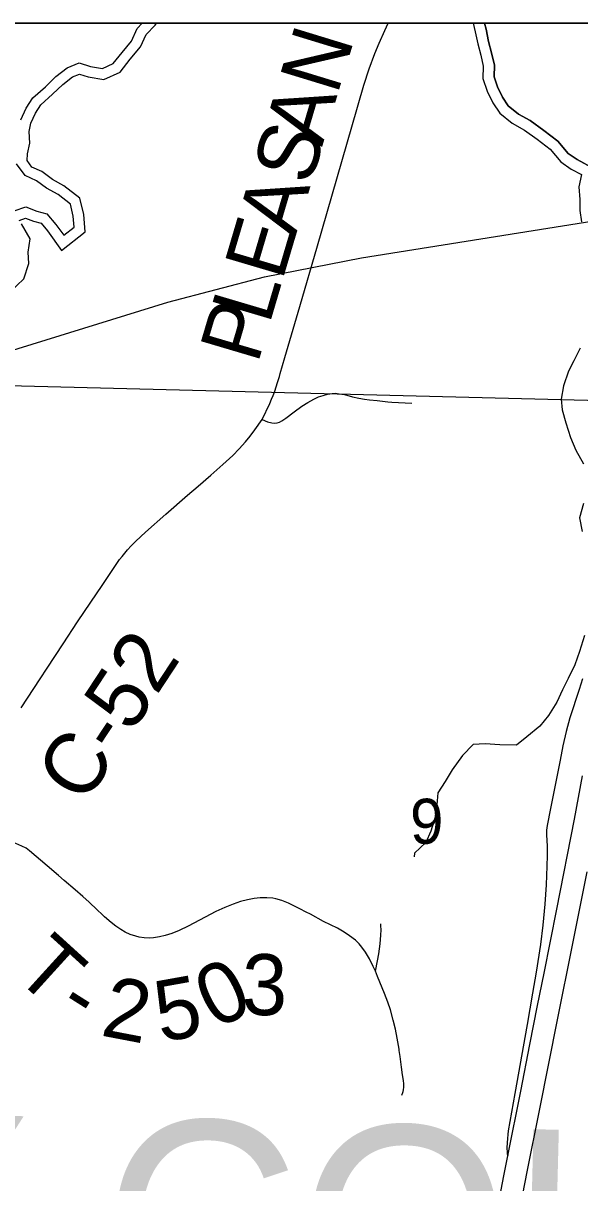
# Model space of a CAD drawing. Extents: x 0 to 34, y 0 to 22.
# Drawn here: x 7.568 to 8.087, y 19.819 to 20.9 of the extents above; entities that cross this region are included whole.
import ezdxf

# ---------------------------------------------------------------- set-up
doc = ezdxf.new("R2010")
doc.units = 0
for name, color, linetype in [('GM_X_Corporation', 7, 'Continuous'), ('GM_X_County_Road', 7, 'Continuous'), ('GM_X_County_Road_Text', 7, 'Continuous'), ('GM_X_County_Text', 7, 'Continuous'), ('GM_X_Interchange_Ramps', 7, 'Continuous'), ('GM_X_Interstate_Route', 7, 'Continuous'), ('GM_X_Major_River', 7, 'Continuous'), ('GM_X_Minor_River', 7, 'Continuous'), ('GM_X_Rail_Line', 7, 'Continuous'), ('GM_X_Section_Text', 7, 'Continuous'), ('GM_X_Township_Road', 7, 'Continuous'), ('GM_X_Township_Road_Text', 7, 'Continuous'), ('SH_Data', 7, 'Continuous')]:
    doc.layers.add(name, color=color, linetype=linetype)

msp = doc.modelspace()

# ---------------------------------------------------------------- linework, layer by layer
at = {"layer": 'GM_X_Corporation'}
for points in [[(8.9, 20.9), (2.1, 20.9), (2.1, 15.6606)], [(8.9, 20.9), (3.3886, 20.9), (3.3869, 20.7918), (3.3724, 19.7263), (3.3691, 19.5041), (3.3642, 18.7005)]]:
    msp.add_lwpolyline(points, dxfattribs=at)
for points in [[(8.4703, 20.9), (7.4509, 20.9), (7.4437, 20.565), (8.4622, 20.5392)], [(8.4622, 20.5392), (8.4405, 19.5256), (7.4231, 19.5526), (7.4437, 20.565)]]:
    msp.add_lwpolyline(points, close=True, dxfattribs=at)
at = {"layer": 'GM_X_County_Road'}
for points in [[(7.8079, 20.5734), (7.8121, 20.5883), (7.8262, 20.636), (7.8425, 20.6926), (7.8746, 20.8035), (7.8859, 20.8422), (7.8908, 20.8576), (7.8959, 20.8716), (7.8999, 20.8813), (7.9052, 20.8932), (7.9085, 20.9)], [(7.7909, 20.5305), (7.798, 20.5455), (7.7998, 20.5496), (7.8011, 20.5529), (7.8027, 20.5572), (7.8054, 20.5651), (7.8071, 20.5706), (7.8079, 20.5734)], [(7.5663, 20.2619), (7.5841, 20.2889), (7.5905, 20.2988), (7.6056, 20.3216), (7.6188, 20.342), (7.6314, 20.3604), (7.6418, 20.3759), (7.6518, 20.391), (7.6581, 20.4001), (7.6604, 20.403), (7.6655, 20.4092), (7.6688, 20.4129), (7.6731, 20.4172), (7.6822, 20.4257), (7.7013, 20.4425), (7.7215, 20.4601), (7.7314, 20.4686), (7.743, 20.4789), (7.7543, 20.4887), (7.7635, 20.497), (7.7697, 20.5032), (7.7756, 20.5097), (7.7799, 20.515), (7.7843, 20.5211), (7.7909, 20.5305)]]:
    msp.add_lwpolyline(points, dxfattribs=at)
at = {"layer": 'GM_X_Interchange_Ramps'}
msp.add_lwpolyline([(8.0896, 20.2891), (8.0864, 20.2791), (8.0777, 20.2525), (8.0742, 20.24), (8.0713, 20.2266), (8.0687, 20.2132), (8.0597, 20.1681), (8.0565, 20.1523), (8.0561, 20.148), (8.056, 20.1436), (8.0565, 20.1331), (8.0565, 20.1244), (8.0563, 20.1144), (8.0556, 20.0971), (8.0544, 20.0791), (8.0526, 20.0593), (8.0504, 20.0414), (8.0464, 20.0156), (8.0431, 19.996), (8.0379, 19.9667), (8.0265, 19.9025), (8.0204, 19.8677), (8.0199, 19.8644), (8.0197, 19.8606), (8.0191, 19.8523), (8.0191, 19.8508), (8.0192, 19.8484), (8.0195, 19.8463), (8.0201, 19.8444)], dxfattribs=at)
at = {"layer": 'GM_X_Interstate_Route'}
for points in [[(7.9586, 19.5353), (7.9699, 19.591), (7.982, 19.6525), (7.9896, 19.6903), (8.0023, 19.7556), (8.0115, 19.8012), (8.0163, 19.8258), (8.0201, 19.8444), (8.032, 19.9048), (8.0405, 19.9481), (8.0477, 19.9846), (8.0537, 20.0145), (8.0655, 20.0742), (8.0821, 20.1583), (8.0896, 20.1986)], [(7.9797, 19.5348), (7.9871, 19.5723), (7.9994, 19.6332), (8.0103, 19.6881), (8.0172, 19.7235), (8.0282, 19.7783), (8.0381, 19.8295), (8.0494, 19.8868), (8.0667, 19.9727), (8.0798, 20.0391), (8.0938, 20.1091)]]:
    msp.add_lwpolyline(points, dxfattribs=at)
at = {"layer": 'GM_X_Major_River'}
for points in [[(7.5645, 20.7162), (7.5704, 20.7184), (7.5778, 20.7155), (7.5849, 20.7135), (7.591, 20.7064), (7.604, 20.6883), (7.626, 20.7056), (7.6247, 20.7218), (7.6209, 20.7368), (7.6062, 20.7484), (7.5955, 20.7544), (7.5856, 20.7617), (7.5764, 20.7659), (7.572, 20.7719), (7.5724, 20.7783), (7.5743, 20.7883), (7.5738, 20.7992), (7.5755, 20.8069), (7.5796, 20.8162), (7.5848, 20.824), (7.5956, 20.8337), (7.6051, 20.843), (7.6141, 20.8499), (7.6208, 20.8526), (7.6287, 20.8499), (7.6435, 20.8475), (7.6585, 20.8544), (7.6681, 20.8665), (7.6775, 20.8781), (7.6829, 20.8896), (7.6911, 20.8983), (7.6924, 20.9)], [(7.5645, 20.7162), (7.5704, 20.7184), (7.5778, 20.7155), (7.5849, 20.7135), (7.591, 20.7064), (7.604, 20.6883), (7.626, 20.7056), (7.6247, 20.7218), (7.6209, 20.7368), (7.6062, 20.7484), (7.5955, 20.7544), (7.5856, 20.7617), (7.5764, 20.7659), (7.572, 20.7719), (7.5724, 20.7783), (7.5743, 20.7883), (7.5738, 20.7992), (7.5755, 20.8069), (7.5796, 20.8162), (7.5848, 20.824), (7.5956, 20.8337), (7.6051, 20.843), (7.6141, 20.8499), (7.6208, 20.8526), (7.6287, 20.8499), (7.6435, 20.8475), (7.6585, 20.8544), (7.6681, 20.8665), (7.6775, 20.8781), (7.6829, 20.8896), (7.6911, 20.8983), (7.6924, 20.9)], [(7.5661, 20.8099), (7.571, 20.8209), (7.5773, 20.8305), (7.5889, 20.8408), (7.5987, 20.8504), (7.6092, 20.8585), (7.6205, 20.8631), (7.6311, 20.8595), (7.6421, 20.8577), (7.6522, 20.8623), (7.6605, 20.8727), (7.6691, 20.8834), (7.6746, 20.8952), (7.6792, 20.9)], [(7.9876, 20.9), (7.9896, 20.892), (7.9919, 20.8807), (7.9947, 20.8701), (7.997, 20.8599), (7.9968, 20.8485), (8.0006, 20.8368), (8.006, 20.8259), (8.0125, 20.8161), (8.024, 20.8067), (8.0354, 20.8004), (8.0472, 20.7918), (8.0593, 20.7825), (8.0693, 20.7708), (8.0791, 20.7641), (8.0886, 20.7589), (8.0861, 20.7475), (8.087, 20.7358), (8.087, 20.7255), (8.0886, 20.715)], [(7.9983, 20.9), (7.9997, 20.8943), (8.002, 20.883), (8.0048, 20.8725), (8.0074, 20.8609), (8.0072, 20.8501), (8.0103, 20.8407), (8.015, 20.8311), (8.0203, 20.8231), (8.0298, 20.8153), (8.0409, 20.8092), (8.0534, 20.8001), (8.0665, 20.79), (8.0762, 20.7786), (8.0846, 20.773), (8.1005, 20.7643)], [(8.1005, 20.7643), (8.0846, 20.773), (8.0762, 20.7786), (8.0665, 20.79), (8.0534, 20.8001), (8.0409, 20.8092), (8.0298, 20.8153), (8.0203, 20.8231), (8.015, 20.8311), (8.0103, 20.8407), (8.0072, 20.8501), (8.0074, 20.8609), (8.0048, 20.8725), (8.002, 20.883), (7.9997, 20.8943), (7.9983, 20.9)], [(7.5597, 20.725), (7.5706, 20.7289), (7.5809, 20.7248), (7.5903, 20.7223), (7.5987, 20.7125), (7.606, 20.7023), (7.6158, 20.71), (7.6149, 20.7202), (7.6122, 20.7312), (7.6008, 20.7402), (7.5901, 20.7461), (7.5806, 20.7532), (7.57, 20.758), (7.562, 20.7689)], [(7.5558, 20.6494), (7.5688, 20.6616), (7.5734, 20.6759), (7.5729, 20.6866), (7.5747, 20.6989), (7.5666, 20.7131)], [(7.5558, 20.6494), (7.5688, 20.6616), (7.5734, 20.6759), (7.5729, 20.6866), (7.5747, 20.6989), (7.5666, 20.7131)]]:
    msp.add_lwpolyline(points, dxfattribs=at)
at = {"layer": 'GM_X_Minor_River'}
for points in [[(8.0874, 20.5971), (8.0815, 20.5853), (8.0766, 20.5758), (8.0718, 20.5621), (8.0697, 20.5496), (8.0705, 20.5397), (8.074, 20.5276), (8.0783, 20.514), (8.0833, 20.502), (8.0906, 20.4892)], [(8.0906, 20.4524), (8.0869, 20.4391), (8.0893, 20.4263)], [(8.0913, 20.3293), (8.0869, 20.3145), (8.0824, 20.3019), (8.0761, 20.2893), (8.0709, 20.2787), (8.0657, 20.2673), (8.0579, 20.2547), (8.0497, 20.2447), (8.0376, 20.2348), (8.0279, 20.2271), (8.0124, 20.2273), (7.9988, 20.2283), (7.9878, 20.2278), (7.9777, 20.2175), (7.968, 20.2041), (7.9616, 20.1934), (7.9546, 20.1828), (7.9539, 20.1714), (7.9521, 20.16), (7.9481, 20.1471), (7.9436, 20.1364), (7.9331, 20.1265), (7.9328, 20.123)]]:
    msp.add_lwpolyline(points, dxfattribs=at)
at = {"layer": 'GM_X_Rail_Line'}
msp.add_lwpolyline([(7.1538, 20.4701), (7.703, 20.6401), (7.7933, 20.6637), (7.8836, 20.6812), (8.2172, 20.7345), (8.3229, 20.7499), (8.4174, 20.7612), (8.4882, 20.7632), (8.5498, 20.7663), (8.589, 20.7738), (8.6669, 20.8033), (8.718, 20.8157), (8.9, 20.8406)], dxfattribs=at)
at = {"layer": 'GM_X_Township_Road'}
for points in [[(7.7909, 20.5305), (7.7961, 20.5285), (7.7999, 20.5275), (7.8024, 20.5273), (7.8049, 20.5275), (7.8072, 20.5283), (7.8094, 20.5294), (7.813, 20.5318), (7.8209, 20.5379), (7.828, 20.543), (7.8337, 20.5466), (7.8391, 20.5496), (7.8436, 20.5517), (7.8477, 20.5531), (7.8518, 20.5542), (7.8561, 20.5548), (7.8593, 20.5551), (7.8629, 20.5547), (7.8677, 20.5538), (7.8753, 20.5519), (7.8812, 20.5504), (7.8863, 20.5496), (7.8911, 20.549), (7.8981, 20.5483), (7.908, 20.5472), (7.9117, 20.5468), (7.9306, 20.5459)], [(7.6013, 20.1057), (7.5906, 20.1147), (7.574, 20.1288), (7.571, 20.131), (7.5671, 20.133), (7.5615, 20.1355), (7.5544, 20.138), (7.5412, 20.1426), (7.5344, 20.1449)], [(7.8965, 20.0166), (7.8944, 20.0208), (7.8909, 20.028), (7.8874, 20.0342), (7.8839, 20.039), (7.8813, 20.0421), (7.8779, 20.0453), (7.8724, 20.0496), (7.8673, 20.0528), (7.8611, 20.0565), (7.8482, 20.0628), (7.8359, 20.0696), (7.832, 20.0715), (7.826, 20.0745), (7.8155, 20.0798), (7.8092, 20.0824), (7.8038, 20.0839), (7.8008, 20.0845), (7.7953, 20.085), (7.7891, 20.0849), (7.7835, 20.0842), (7.7774, 20.083), (7.7708, 20.0813), (7.7638, 20.0789), (7.7563, 20.0759), (7.7479, 20.072), (7.7379, 20.0668), (7.722, 20.0584), (7.7136, 20.0544), (7.7067, 20.0516), (7.7007, 20.0497), (7.6953, 20.0484), (7.6898, 20.0475), (7.6861, 20.0473), (7.6811, 20.0475), (7.6762, 20.0483), (7.6732, 20.049), (7.6679, 20.0508), (7.6634, 20.0529), (7.6591, 20.0554), (7.6545, 20.0586), (7.6501, 20.062), (7.6441, 20.0673), (7.6351, 20.0758), (7.6319, 20.0787), (7.6297, 20.0808), (7.6237, 20.0861), (7.6166, 20.0922), (7.6063, 20.1011), (7.6013, 20.1057)], [(7.8965, 20.0166), (7.8984, 20.0262), (7.8997, 20.0328), (7.9009, 20.042), (7.9016, 20.0501), (7.9018, 20.055), (7.9017, 20.0588), (7.9015, 20.0606)], [(7.9211, 19.9011), (7.9221, 19.9033), (7.9224, 19.9044), (7.9228, 19.906), (7.9231, 19.9084), (7.9231, 19.9114), (7.9227, 19.9145), (7.9219, 19.92), (7.9209, 19.9272), (7.9198, 19.9345), (7.9195, 19.937), (7.9188, 19.9425), (7.9186, 19.9437), (7.9169, 19.9541), (7.9153, 19.9626), (7.9132, 19.971), (7.9105, 19.9805), (7.9081, 19.9876), (7.905, 19.9956), (7.8986, 20.0116), (7.8965, 20.0166)]]:
    msp.add_lwpolyline(points, dxfattribs=at)
at = {"layer": 'SH_Data'}
msp.add_line((2.1, 20.9), (8.9, 20.9), dxfattribs=at)

# ---------------------------------------------------------------- texts
at = {"layer": 'GM_X_County_Road_Text'}
for s, height, rotation, p in [('N', 0.0568, 73.0023, (7.8609, 20.8322)), ('A', 0.0568, 73.5007, (7.8468, 20.7844)), ('S', 0.0568, 73.5044, (7.8359, 20.7477)), ('A', 0.0568, 73.5082, (7.8217, 20.6997)), ('E', 0.0568, 73.506, (7.8096, 20.659)), ('L', 0.0568, 73.5047, (7.7976, 20.6182)), ('P', 0.0568, 73.5044, (7.7867, 20.5815)), ('C-52', 0.05682, 56.6824, (7.6252, 20.1705))]:
    msp.add_text(s, height=height, rotation=rotation, dxfattribs=at).set_placement(p)
at = {"layer": 'GM_X_County_Text'}
msp.add_text('GUERNSEY COUNTY', height=0.189394, rotation=358.543, dxfattribs=at).set_placement((6.1485, 19.728))
at = {"layer": 'GM_X_Section_Text'}
msp.add_text('9', height=0.0419, rotation=0, dxfattribs=at).set_placement((7.9288, 20.1353))
at = {"layer": 'GM_X_Township_Road_Text'}
for s, rotation, p in [('T', 317.7541, (7.5581, 20.0128)), ('0', 26.3936, (7.7473, 19.9618)), ('3', 359.3443, (7.7718, 19.9758)), ('2', 349.1835, (7.6393, 19.9568)), ('5', 10.1897, (7.6963, 19.9501)), ('-', 327.7845, (7.5982, 19.9777))]:
    msp.add_text(s, height=0.0568, rotation=rotation, dxfattribs=at).set_placement(p)

doc.saveas('drawing.dxf')
